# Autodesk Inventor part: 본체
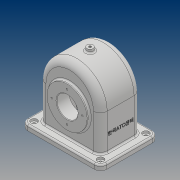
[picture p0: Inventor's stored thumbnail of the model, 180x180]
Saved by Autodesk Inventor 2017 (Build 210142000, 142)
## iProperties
Part Number: 본체
Material: 일반
Document SubType Name: Modeling
Designer: 20
Density: 1 g/cm^3
Appearance: 기본값
Mass: 404.475 g
Surface Area: 1182.21 cm^2
Volume: 404.475 cm^3
Author: 20
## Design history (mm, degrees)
sketch "스케치1"
  geometry: L1 (81.2, 0)-(-81.2, 0) reference; L2 (0, -105.2)-(0, 85.2) reference; L3 (58, -78)-(-58, -78); L4 (58, 0)-(58, -78); L5 (-58, 0)-(-58, -78); A1 r 58 centre (0, 0) between (58, 0) and (-58, 0); 1 further point
  constraints: 6 end point, 2 point on circle, 2 point on line, 2 vertical, 1 centre point, 1 coincident, 1 parallel, 1 tangent
  dimensions: "d0" = 78 distance between parallel lines of L1 L3; "d3" = 116 diameter of A1
extrude "돌출1" new body sketch "스케치1" stored distance "d4" = 77; taper "d5" = 0 deg
sketch "스케치2"
  geometry: L1 (81.2, 0)-(-81.2, 0) reference; L2 (0, -105.2)-(0, 85.2) reference; L3 (52, 0)-(52, -78); L4 (-58, -78)-(58, -78) reference; L5 (-52, 0)-(-52, -78); L6 (-52, -78)-(52, -78); A1 r 52 centre (0, 0) between (52, 0) and (-52, 0); A2 r 58 centre (0, 0) between (58, 0) and (-58, 0) reference; 1 further point
  constraints: 6 end point, 4 point on line, 2 point on circle, 2 vertical, 1 centre point, 1 coincident, 1 horizontal, 1 tangent
  dimensions: "d6" = 6 radial gap between concentric circles of A2 A1
extrude "돌출3" cut sketch "스케치2" stored distance "d14" = 67; taper "d15" = 0 deg
node "작업 평면1"
sketch "스케치3"
  geometry: L1 (-81.2, 0)-(81.2, 0) reference; L2 (0, -53.9)-(0, 53.9) reference; L3 (-75, -55)-(75, -55); L4 (75, -55)-(75, 55); L5 (75, 55)-(-75, 55); L6 (-75, 55)-(-75, -55); L7 (52, -33.5)-(52, 33.5) reference; L8 (52, -33.5)-(-52, -33.5) reference; L9 (-52, -33.5)-(-52, 33.5) reference; L10 (-52, 33.5)-(52, 33.5) reference; 1 further point
  constraints: 8 end point, 2 parallel, 1 horizontal, 1 perpendicular
  dimensions: "d10" = 110 distance of L5.end L3.start; "d11" = 150 distance of L4.end L5.end; "d12" = 75 distance between parallel lines of L2 L6; "d13" = 55 distance between parallel lines of L1 L3
extrude "돌출4" join sketch "스케치3" distance "d16" = 10; taper "d17" = 0 deg
sketch "스케치4"
  geometry: L1 (-105, 0)-(105, 0) reference; L2 (0, -105.2)-(0, 85.2) reference; L3 (-75, -78)-(75, -78) reference; C1 r 38 at (0, -13); 1 further point
  constraints: 1 centre point, 1 point on line
  dimensions: "d18" = 65 distance from line of L3 C1.centre; "d19" = 76 diameter of C1
extrude "돌출5" join sketch "스케치4" distance "d20" = 5; taper "d21" = 0 deg
sketch "스케치5"
  geometry: L1 (-105, 0)-(105, 0) reference; L2 (0, 105.2)-(0, -85.2) reference; L3 (75, 78)-(-75, 78) reference; C1 r 38 at (0, 13); 1 further point
  constraints: 1 centre point, 1 point on line
  dimensions: "d22" = 65 distance from line of L3 C1.centre; "d23" = 76 diameter of C1
extrude "돌출6" join sketch "스케치5" distance "d24" = 10; taper "d25" = 0 deg
sketch "스케치6"
  geometry: L1 (-105, 0)-(105, 0) reference; L2 (0, 105.2)-(0, -85.2) reference; L3 (-75, 78)-(75, 78) reference; C1 r 28 at (0, 13); 1 further point
  constraints: 1 centre point, 1 point on line
  dimensions: "d26" = 65 distance from line of L3 C1.centre; "d27" = 56 diameter of C1
extrude "돌출7" join sketch "스케치6" distance "d28" = 14; taper "d29" = 0 deg
feature "면 기울기1" dims angle "d30" = 40 deg
sketch "스케치7"
  geometry: C1 r 38 at (0, 0) reference; C2 r 20 at (0, 0); 1 further point
  constraints: 1 centre point, 1 coincident
  dimensions: "d31" = 40 diameter of C2
extrude "돌출8" cut sketch "스케치7" stored distance "d32" = 14; taper "d33" = 0 deg
node "작업 평면2"
sketch "스케치8"
  geometry: L1 (0, -77)-(0, 77) reference; L2 (-105, 0)-(105, 0) reference; L3 (-75, 55)-(-75, -55) reference; C1 r 6 at (0, 0); 1 further point
  constraints: 1 centre point, 1 midpoint
  dimensions: "d35" = 75 distance from line of L3 C1.centre; "d36" = 12 diameter of C1
extrude "돌출9" join sketch "스케치8" stored distance "d37" = 14; taper "d38" = 5 deg
fillet "모깎기1" dims "d39" = 12
sketch "스케치10"
  geometry: L1 (-105, 0)-(105, 0) reference; C1 r 6 at (-63, -43); A1 r 12 centre (-63, -43) between (-75, -43) and (-63, -55) reference; 1 further point
  constraints: 1 centre point, 1 coincident
  dimensions: "d40" = 12 diameter of C1
hole "구멍1" sketch "스케치10" at (-63, -43) diameter "d41" = 5; stored, may be unused: countersink angle "d45" = 90 deg, drill point angle "d47" = 0 deg; dims "d42" = 6, "d43" = 12, "d44" = 4, "d46" = 8
sketch "스케치11" dims "d48" = 58
  geometry: L1 (-105, 13)-(105, 13) reference; L2 (0, -93.4)-(0, 105.4) reference; C1 r 38 at (0, 0) reference; C2 r 2 at (0, 29); 2 further points
  constraints: 1 centre point, 1 coincident, 1 point on line, 1 vertical alignment, 2 other
  dimensions: "d49" = 4 diameter of C2
hole "구멍2" sketch "스케치11" at (0, 29) diameter "d50" = 3.242; stored, may be unused: countersink angle "d54" = 90 deg, drill point angle "d56" = 118 deg; dims "d51" = 8, "d52" = 12, "d53" = 4, "d55" = 10
sketch "스케치12" dims "d60" = 58
  geometry: L1 (0, 93.4)-(0, -105.4) reference; C1 r 38 at (0, 0) reference; C2 r 2 at (0, -29); 2 further points
  constraints: 1 centre point, 1 coincident, 1 point on line, 1 vertical alignment, 2 other
  dimensions: "d61" = 4 diameter of C2
hole "구멍3" sketch "스케치12" at (0, -29) diameter "d62" = 3.242; stored, may be unused: countersink angle "d66" = 90 deg, drill point angle "d68" = 118 deg; dims "d63" = 8, "d64" = 12, "d65" = 4, "d67" = 10
sketch "스케치13"
  geometry: C1 r 6 at (0, 0) reference; C2 r 2.5 at (0, 0); 1 further point
  constraints: 1 centre point, 1 coincident
  dimensions: "d72" = 5 diameter of C2
hole "구멍4" sketch "스케치13" at (0, 0) diameter "d73" = 4.459; stored, may be unused: countersink angle "d77" = 90 deg, drill point angle "d79" = 0 deg; dims "d74" = 10, "d75" = 12, "d76" = 4, "d78" = 12.8
fillet "모깎기2" dims "d80" = 3
fillet "모깎기3" dims "d81" = 13
fillet "모깎기4" dims "d82" = 8
fillet "모깎기5" dims "d83" = 3
fillet "모깎기6" dims "d84" = 3
fillet "모깎기7" dims "d85" = 3
chamfer "모따기1" distance "d86" = 1; stored, may be unused: second distance "d87" = 2, angle "d88" = 45 deg
fillet "모깎기8" dims "d89" = 3
sketch "스케치14"
  geometry: L1 (78, -17.5)-(78, 68.5) reference; L2 (0, -13)-(65, -13) reference; 2 further points
  constraints: 1 other
  dimensions: "d90" = 40 distance from line of L1 point (38, 25.5); "d91" = 38.5 distance from line of L2 point (38, 25.5)
feature "엠보싱1" sketch "스케치14" dims "d92" = 0.5, "d93" = 0
node "솔리드1"
mirror "미러1"
mirror "미러2"
pattern_circular "원형 패턴1" dims angle "d58" = 360 deg
pattern_circular "원형 패턴2" dims angle "d70" = 360 deg
node "투영된 루프1"
other parameters: "d9" = -78, "d34" = 142
